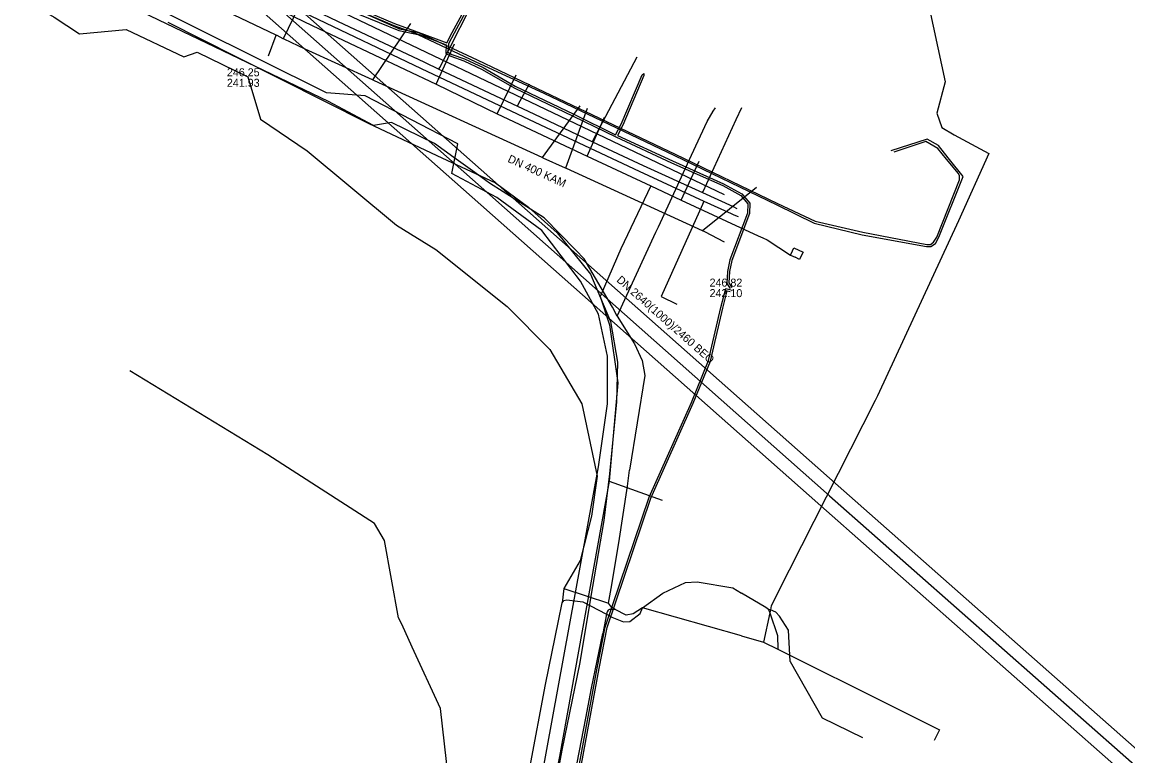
# Model space of a CAD drawing. Extents: x -600309 to -598967, y -1161267 to -1160292.
# Drawn here: x -600071.9 to -599961.4, y -1160914.1 to -1160840.8 of the extents above; entities that cross this region are included whole.
import ezdxf

# ---------------------------------------------------------------- set-up
doc = ezdxf.new("R2010")
doc.units = 0
for name, color, linetype in [('Vrstva 1', 7, 'Continuous'), ('Vrstva 12', 7, 'Continuous'), ('Vrstva 13', 7, 'Continuous'), ('Vrstva 19', 7, 'Continuous'), ('Vrstva 42', 7, 'Continuous'), ('Vrstva 44', 7, 'Continuous'), ('Vrstva 5', 7, 'Continuous'), ('Vrstva 51', 7, 'Continuous'), ('Vrstva 55', 7, 'Continuous'), ('Vrstva 58', 7, 'Continuous'), ('Vrstva 6', 7, 'Continuous'), ('Vrstva 8', 7, 'Continuous'), ('Vrstva 9', 7, 'Continuous')]:
    doc.layers.add(name, color=color, linetype=linetype)

msp = doc.modelspace()

# ---------------------------------------------------------------- linework, layer by layer
at = {"layer": 'Vrstva 1'}
msp.add_lwpolyline([(-600047.28, -1160844.11), (-600046.52, -1160842.06)], dxfattribs=at)
at = {"layer": 'Vrstva 12'}
for points in [[(-599972.93, -1160813.79), (-599978.49, -1160823.66), (-599978.82, -1160825.74), (-599980.3, -1160827.69), (-599982.73, -1160833.94), (-599981.57, -1160837.73), (-599979.64, -1160846.74), (-599980.47, -1160849.86), (-599979.98, -1160851.29), (-599978.75, -1160852.02)], [(-600091.66, -1160840.85), (-600091.96, -1160840.68), (-600094.05, -1160839.49), (-600086.91, -1160827.62), (-600086.16, -1160830.54), (-600077.15, -1160835.41), (-600068.71, -1160840.25), (-600066.18, -1160841.92), (-600061.52, -1160841.51), (-600055.76, -1160844.23), (-600054.42, -1160843.75), (-600049.36, -1160846.22)], [(-600028.74, -1160854.29), (-600030.68, -1160852.89), (-600035, -1160850.8), (-600036.79, -1160851.1), (-600041.29, -1160848.69), (-600064.77, -1160837.41)], [(-600049.36, -1160846.22), (-600048.09, -1160850.47)], [(-600003.44, -1160850.69), (-600002.82, -1160849.65)], [(-600002.82, -1160849.65), (-600002.61, -1160849.31)], [(-600048.09, -1160850.47), (-600043.43, -1160853.61), (-600034.48, -1160861.05), (-600030.54, -1160863.47), (-600023.43, -1160869.19), (-600019.17, -1160873.47), (-600015.95, -1160878.91), (-600014.41, -1160886.15), (-600014.98, -1160890.14), (-600016.13, -1160894.58), (-600017.76, -1160897.36)], [(-600005, -1160854.04), (-600003.44, -1160850.69)], [(-599978.75, -1160852.02), (-599975.28, -1160853.9), (-599978.3, -1160860.6), (-599986.39, -1160878.12), (-599986.62, -1160878.58), (-599995.22, -1160895.54), (-599997.03, -1160899.1), (-599997.11, -1160899.5)], [(-600026.67, -1160855.77), (-600028.74, -1160854.29)], [(-600008.57, -1160861.76), (-600008.31, -1160861.22), (-600005.8, -1160855.77), (-600005, -1160854.04)], [(-600012.43, -1160870.13), (-600012.89, -1160869.23), (-600015.71, -1160864.41), (-600016.55, -1160863.56), (-600019.74, -1160860.33), (-600025.19, -1160856.84), (-600026.67, -1160855.77)], [(-600012.43, -1160870.13), (-600008.57, -1160861.76)], [(-600012.43, -1160870.13), (-600010.68, -1160872.91), (-600009.94, -1160874.58), (-600009.67, -1160876.07), (-600011.18, -1160885.55)], [(-600011.38, -1160887.14), (-600011.18, -1160885.55)], [(-600013.04, -1160897.36), (-600012.27, -1160892.8), (-600011.38, -1160887.14)], [(-600017.76, -1160897.36), (-600017.94, -1160898.79)], [(-600017.76, -1160897.36), (-600013.28, -1160898.83)], [(-600013.28, -1160898.83), (-600013.04, -1160897.36)], [(-600009.88, -1160899.29), (-600007.86, -1160897.82), (-600005.6, -1160896.75)], [(-600005.6, -1160896.75), (-600004.42, -1160896.7), (-600000.86, -1160897.31), (-600000, -1160897.82)], [(-600017.94, -1160898.79), (-600017.76, -1160898.57), (-600017.45, -1160898.48), (-600015.86, -1160898.69), (-600013.49, -1160899.94)], [(-599997.29, -1160899.45), (-599997.56, -1160899.26), (-600000, -1160897.82)], [(-600018.3, -1160900.6), (-600017.94, -1160898.79)], [(-600013.49, -1160899.94), (-600012.96, -1160900.22), (-600011.78, -1160900.68), (-600011.17, -1160900.67), (-600010.12, -1160899.85), (-600009.88, -1160899.29)], [(-600012.62, -1160899.45), (-600013.19, -1160899.47), (-600013.33, -1160899.52), (-600013.44, -1160899.7), (-600013.49, -1160899.94)], [(-600012.62, -1160899.45), (-600013.01, -1160899.24), (-600013.28, -1160898.83)], [(-600009.88, -1160899.29), (-600010.84, -1160899.9), (-600011.53, -1160900.02), (-600012.62, -1160899.45)], [(-600000, -1160902.1), (-600009.88, -1160899.29)], [(-599997.17, -1160899.79), (-599997.79, -1160902.73)], [(-599997.29, -1160899.45), (-599997.17, -1160899.79)], [(-599997.11, -1160899.5), (-599997.29, -1160899.45)], [(-599997.11, -1160899.5), (-599997.17, -1160899.79)], [(-599997.17, -1160899.79), (-599996.39, -1160902.05), (-599996.38, -1160903.43)], [(-599995.17, -1160904.03), (-599995.3, -1160901.52), (-599996.2, -1160900.13), (-599996.56, -1160899.73), (-599997.11, -1160899.5)], [(-600021.41, -1160915.63), (-600021.16, -1160915.29), (-600019.58, -1160906.96), (-600018.3, -1160900.6)], [(-600013.49, -1160899.94), (-600013.87, -1160901.87)], [(-600022.47, -1160946.7), (-600022.17, -1160944.27), (-600018.18, -1160923.89), (-600015.57, -1160910.31), (-600014.99, -1160907.31), (-600013.87, -1160901.87)], [(-600000, -1160902.1), (-599997.79, -1160902.73)], [(-599997.79, -1160902.73), (-599996.38, -1160903.43)], [(-599996.38, -1160903.43), (-599995.17, -1160904.03)], [(-599995.15, -1160904.67), (-599995.17, -1160904.03)], [(-599995.17, -1160904.03), (-599986.06, -1160908.56)], [(-599995.15, -1160904.67), (-599991.92, -1160910.28)], [(-599986.06, -1160908.56), (-599980.21, -1160911.49), (-599980.74, -1160912.54)], [(-599991.92, -1160910.28), (-599987.89, -1160912.27)]]:
    msp.add_lwpolyline(points, dxfattribs=at)
at = {"layer": 'Vrstva 13'}
for p, q in [((-600001.04, -1160859.88), (-600000.77, -1160860)), ((-600000.84, -1160859.2), (-600000.47, -1160859.39)), ((-600000.77, -1160860), (-600000.34, -1160860.18))]:
    msp.add_line(p, q, dxfattribs=at)
for points in [[(-600075.2, -1160823.45), (-600070.43, -1160825.81), (-600064.32, -1160828.96), (-600054.38, -1160833.93), (-600053.49, -1160834.37), (-600042.61, -1160839.61), (-600040.39, -1160840.66), (-600031.7, -1160844.77), (-600030.24, -1160845.46), (-600022.4, -1160849.16), (-600020.77, -1160849.93), (-600014.89, -1160852.71), (-600009.83, -1160855.1), (-600003.91, -1160857.8), (-600000.84, -1160859.2)], [(-600075.91, -1160823.87), (-600070.68, -1160826.48), (-600064.69, -1160829.36), (-600053.95, -1160834.9), (-600043.04, -1160840.13), (-600032.02, -1160845.38), (-600021.22, -1160850.5), (-600010.24, -1160855.65), (-600003.77, -1160858.66), (-600001.04, -1160859.88)], [(-600030.24, -1160845.46), (-600030.15, -1160845.28), (-600026.13, -1160837.32)], [(-600014.89, -1160852.71), (-600014.82, -1160852.57), (-600010.42, -1160844.22)], [(-600022.4, -1160849.16), (-600022.31, -1160849), (-600021.18, -1160846.93)], [(-600003.91, -1160857.8), (-600003.84, -1160857.67), (-600000.54, -1160850.48), (-599999.98, -1160849.28)], [(-600003.77, -1160858.66), (-600003.89, -1160858.98), (-600008.03, -1160868.18), (-600006.47, -1160868.93)]]:
    msp.add_lwpolyline(points, dxfattribs=at)
at = {"layer": 'Vrstva 19'}
for points in [[(-600070.24, -1160827.89), (-600070.04, -1160828.01), (-600069.81, -1160828.12), (-600069.47, -1160828.3), (-600069.14, -1160828.43), (-600068.7, -1160828.63), (-600067.42, -1160829.27), (-600057.74, -1160833.93), (-600049.35, -1160838.07), (-600045.63, -1160839.81), (-600042.92, -1160841.09), (-600030.52, -1160846.95), (-600024.43, -1160849.93), (-600015.44, -1160854.15), (-600009.05, -1160857.12), (-600006.04, -1160858.54), (-599998.33, -1160862.11), (-599997.88, -1160862.32)], [(-600030.52, -1160846.95), (-600028.7, -1160842.91)], [(-600024.43, -1160849.93), (-600022.53, -1160846.02)], [(-600015.44, -1160854.15), (-600013.69, -1160850.24)], [(-600006.04, -1160858.54), (-600004.23, -1160854.64)], [(-600009.05, -1160857.12), (-600012.05, -1160863.42), (-600014.13, -1160868.17), (-600013.18, -1160871.01), (-600012.35, -1160876.81), (-600013.23, -1160886.63), (-600018.2, -1160914.15), (-600021.52, -1160930.87), (-600024.48, -1160949.96), (-600028.56, -1160971.82), (-600029.11, -1160974.77), (-600029.14, -1160974.99), (-600029.72, -1160978.77), (-600031.16, -1160990.94), (-600031.59, -1160993.91), (-600031.97, -1160996.52)], [(-599997.88, -1160862.32), (-599997.42, -1160862.53)], [(-599997.42, -1160862.53), (-599995.1, -1160864.04), (-599994.89, -1160863.6), (-599994.76, -1160863.32), (-599993.85, -1160863.75), (-599994.03, -1160864.11), (-599994.2, -1160864.47), (-599994.65, -1160864.25)], [(-599995.1, -1160864.04), (-599994.65, -1160864.25)], [(-600013.23, -1160886.63), (-600007.94, -1160888.52)]]:
    msp.add_lwpolyline(points, dxfattribs=at)
at = {"layer": 'Vrstva 42'}
for points in [[(-600037.52, -1160839.7), (-600034.67, -1160840.9), (-600031.69, -1160841.99), (-600029.98, -1160842.62), (-600029.46, -1160842.81), (-600028.91, -1160841.79), (-600027.1, -1160838.39)], [(-600026.93, -1160838.48), (-600028.72, -1160841.85), (-600029.3, -1160842.94), (-600029.37, -1160843.77), (-600028.96, -1160843.98), (-600027.69, -1160844.43), (-600025.81, -1160845.3), (-600022.63, -1160847.15), (-600016.76, -1160849.97), (-600012.58, -1160852.01), (-600012.04, -1160850.95), (-600009.94, -1160846.02), (-600009.77, -1160845.88), (-600009.76, -1160846.1), (-600011.85, -1160851.04), (-600012.4, -1160852.09), (-600006.9, -1160854.63), (-600001.79, -1160856.92), (-599999.96, -1160857.92), (-599999.16, -1160858.84), (-599999.2, -1160859.88), (-600000.96, -1160864.58), (-600001.21, -1160865.69), (-600001.26, -1160866.82), (-600000.98, -1160867.28)], [(-600037.6, -1160839.88), (-600034.75, -1160841.08), (-600031.75, -1160842.17), (-600029.51, -1160843.01), (-600029.57, -1160843.89), (-600029.04, -1160844.16), (-600027.77, -1160844.61), (-600025.91, -1160845.48), (-600022.73, -1160847.33), (-600016.84, -1160850.15), (-600012.57, -1160852.23), (-600006.98, -1160854.81), (-600001.87, -1160857.1), (-600000.08, -1160858.08), (-599999.36, -1160858.92), (-599999.4, -1160859.84), (-600001.16, -1160864.52), (-600001.41, -1160865.67), (-600001.46, -1160866.88), (-600001.14, -1160867.38)], [(-600028.08, -1160984.54), (-600027.7, -1160983.77), (-600026.59, -1160971.91), (-600024.56, -1160960.19), (-600024.34, -1160958.81), (-600022.15, -1160944.86), (-600021.22, -1160941.76), (-600018.11, -1160925.36), (-600014.43, -1160905.31), (-600013.63, -1160901.22), (-600009.24, -1160888.24), (-600005, -1160878.77), (-600003.3, -1160874.58), (-600002.06, -1160869.29), (-600001.57, -1160867.37), (-600001.04, -1160867.51)], [(-600027.88, -1160984.58), (-600027.5, -1160983.79), (-600026.4, -1160971.94), (-600024.37, -1160960.23), (-600024.14, -1160958.84), (-600021.96, -1160944.9), (-600021.03, -1160941.81), (-600017.92, -1160925.39), (-600014.23, -1160905.35), (-600013.44, -1160901.27), (-600009.05, -1160888.32), (-600004.82, -1160878.85), (-600003.11, -1160874.64), (-600001.87, -1160869.34), (-600001.42, -1160867.62), (-600001.12, -1160867.69)]]:
    msp.add_lwpolyline(points, dxfattribs=at)
at = {"layer": 'Vrstva 44'}
for points in [[(-600038.19, -1160840.01), (-600034.25, -1160841.61), (-600032.35, -1160841.99), (-600026.55, -1160844.71), (-600019.76, -1160847.85), (-600006.69, -1160854.1), (-599996.48, -1160859.02), (-599992.72, -1160860.85), (-599987.92, -1160862), (-599981.52, -1160863.17), (-599981.06, -1160863.18), (-599980.61, -1160862.87), (-599980.28, -1160862.26), (-599977.83, -1160856.17), (-599979.34, -1160854.31), (-599980.29, -1160853.09), (-599981.45, -1160852.46), (-599985.06, -1160853.63)], [(-600038.09, -1160839.71), (-600034.19, -1160841.43), (-600032.3, -1160841.8), (-600026.43, -1160844.51), (-600019.73, -1160847.71), (-600006.62, -1160853.94), (-599996.4, -1160858.88), (-599992.62, -1160860.65), (-599987.86, -1160861.75), (-599981.47, -1160862.98), (-599981.09, -1160862.99), (-599980.79, -1160862.76), (-599980.47, -1160862.24), (-599978.2, -1160856.51), (-599978.21, -1160856.13), (-599978.29, -1160855.87), (-599979.49, -1160854.44), (-599980.38, -1160853.4), (-599981.56, -1160852.69), (-599984.76, -1160853.76)]]:
    msp.add_lwpolyline(points, dxfattribs=at)
at = {"layer": 'Vrstva 5'}
msp.add_lwpolyline([(-600308.54, -1160606.85), (-600293.71, -1160619.85), (-600261.21, -1160648.62), (-600227.37, -1160678.98), (-600193.6, -1160708.94), (-600158.76, -1160739.74), (-600125.82, -1160768.91), (-600092.25, -1160798.69), (-600058.95, -1160828.11), (-600025.17, -1160858.03), (-599991.2, -1160888.1), (-599957.35, -1160917.96), (-599922.99, -1160948.3), (-599888.58, -1160978.69), (-599854.96, -1161008.36), (-599821.09, -1161038.33), (-599787.86, -1161071.18), (-599769.32, -1161098.46), (-599756.94, -1161125.32), (-599745.87, -1161159.88), (-599726.48, -1161222.14), (-599721.97, -1161234.03), (-599710.42, -1161267.03)], dxfattribs=at)
at = {"layer": 'Vrstva 51'}
msp.add_lwpolyline([(-600029.2, -1160995.83), (-600029.51, -1160995.11), (-600029.59, -1160994.65), (-600028.77, -1160988.2), (-600028.66, -1160978.14), (-600028.77, -1160969.29), (-600028.68, -1160967.03), (-600026.93, -1160957.82), (-600026.25, -1160954.04), (-600025.05, -1160948.56), (-600024.5, -1160945.47), (-600024.26, -1160944.09), (-600028.12, -1160937.72), (-600028.59, -1160929), (-600028.46, -1160923.79), (-600030.09, -1160909.34), (-600032.92, -1160903.21), (-600033.96, -1160900.94), (-600034.27, -1160900.28), (-600035.69, -1160892.55), (-600036.68, -1160890.87), (-600047.34, -1160884.01), (-600061.13, -1160875.61)], dxfattribs=at)
at = {"layer": 'Vrstva 55'}
for points in [[(-600038.64, -1160994.33), (-600031.63, -1160979.98), (-600014.29, -1160885.2), (-600013.39, -1160878.92), (-600013.39, -1160874.14), (-600014.29, -1160869.95), (-600016.08, -1160866.66), (-600019.97, -1160861.58), (-600024.45, -1160858.29), (-600028.94, -1160855.9), (-600028.34, -1160852.91), (-600037.61, -1160848.13), (-600041.5, -1160847.83), (-600061.23, -1160837.96), (-600071.2, -1160833.38), (-600081.26, -1160829.89), (-600090.32, -1160825.04), (-600085.27, -1160815.83)], [(-600054.61, -1160832.69), (-600001.73, -1160857.99)]]:
    msp.add_lwpolyline(points, dxfattribs=at)
at = {"layer": 'Vrstva 58'}
for points in [[(-600057.36, -1160840.75), (-600050.56, -1160844.19), (-600037.33, -1160850.84), (-600030.47, -1160854.1), (-600024.58, -1160856.83), (-600021.3, -1160859.25)], [(-600021.3, -1160859.25), (-600018.42, -1160861.81), (-600015.09, -1160865.96), (-600013.11, -1160870.69), (-600012.4, -1160874.75), (-600012.5, -1160878.7), (-600013.21, -1160885.89), (-600013.77, -1160890.56), (-600015.09, -1160898.33), (-600016.17, -1160904.75), (-600017.96, -1160913.53), (-600019.34, -1160920.89)], [(-600029.21, -1160995.84), (-600029.51, -1160995.11), (-600029.59, -1160994.65), (-600028.77, -1160988.2), (-600028.66, -1160978.14), (-600028.77, -1160969.29), (-600028.68, -1160967.03), (-600026.93, -1160957.82), (-600026.25, -1160954.04), (-600025.05, -1160948.56), (-600024.5, -1160945.47), (-600024.26, -1160944.09), (-600028.12, -1160937.72), (-600028.59, -1160929), (-600028.46, -1160923.79), (-600030.09, -1160909.34), (-600032.92, -1160903.21), (-600033.96, -1160900.94), (-600034.27, -1160900.28), (-600035.69, -1160892.55), (-600036.68, -1160890.87), (-600047.34, -1160884.01), (-600061.13, -1160875.61)]]:
    msp.add_lwpolyline(points, dxfattribs=at)
at = {"layer": 'Vrstva 6'}
for points in [[(-600308.54, -1160605.1), (-600292.84, -1160618.86), (-600260.33, -1160647.63), (-600226.49, -1160677.99), (-600192.72, -1160707.95), (-600157.88, -1160738.75), (-600124.94, -1160767.92), (-600091.37, -1160797.7), (-600058.07, -1160827.12), (-600024.29, -1160857.04), (-599990.32, -1160887.11), (-599956.48, -1160916.97), (-599922.11, -1160947.31), (-599887.7, -1160977.7), (-599854.08, -1161007.37), (-599820.19, -1161037.36), (-599786.84, -1161070.33), (-599768.16, -1161097.81), (-599755.71, -1161124.84), (-599744.61, -1161159.48), (-599725.23, -1161221.71), (-599720.73, -1161233.58), (-599709.02, -1161267.03)], [(-599711.82, -1161267.03), (-599723.21, -1161234.48), (-599727.73, -1161222.57), (-599747.13, -1161160.27), (-599758.17, -1161125.8), (-599770.48, -1161099.11), (-599788.88, -1161072.03), (-599821.99, -1161039.3), (-599855.84, -1161009.35), (-599889.46, -1160979.68), (-599923.87, -1160949.29), (-599958.23, -1160918.95), (-599992.08, -1160889.09), (-600026.05, -1160859.02), (-600059.83, -1160829.1), (-600093.13, -1160799.68), (-600126.7, -1160769.9), (-600159.64, -1160740.73), (-600194.48, -1160709.93), (-600228.25, -1160679.97), (-600262.09, -1160649.61), (-600294.58, -1160620.84), (-600308.54, -1160608.61)]]:
    msp.add_lwpolyline(points, dxfattribs=at)
at = {"layer": 'Vrstva 9'}
for p, q in [((-600042.95, -1160836.49), (-600045.8, -1160842.41)), ((-600033.09, -1160840.91), (-600036.87, -1160846.54)), ((-600016.16, -1160849.12), (-600019.91, -1160854.29)), ((-600015.44, -1160849.39), (-600017.59, -1160855.35)), ((-599998.51, -1160857.3), (-600003.91, -1160861.61))]:
    msp.add_line(p, q, dxfattribs=at)
for points in [[(-600043.6, -1160843.46), (-600045.71, -1160842.45), (-600045.8, -1160842.41), (-600046.43, -1160842.1), (-600046.52, -1160842.06), (-600052.87, -1160839.03), (-600052.97, -1160838.98), (-600070.39, -1160830.66), (-600070.56, -1160830.58), (-600082.75, -1160824.76)], [(-600001.71, -1160862.74), (-600003.68, -1160861.73), (-600003.91, -1160861.61), (-600017.49, -1160855.4), (-600017.59, -1160855.35), (-600019.81, -1160854.34), (-600019.91, -1160854.29), (-600036.7, -1160846.61), (-600036.87, -1160846.54), (-600043.6, -1160843.46)]]:
    msp.add_lwpolyline(points, dxfattribs=at)

# ---------------------------------------------------------------- texts
at = {"layer": 'Vrstva 12'}
for s, p in [('246.25', (-600051.44, -1160846.17)), ('241.93', (-600051.44, -1160847.22)), ('246.82', (-600003.19, -1160867.19)), ('242.10', (-600003.19, -1160868.24))]:
    msp.add_text(s, height=0.8, dxfattribs=at).set_placement(p)
msp.add_text('DN 400 KAM', height=0.8, rotation=335.4095, dxfattribs=at).set_placement((-600023.44, -1160854.7))
at = {"layer": 'Vrstva 8'}
msp.add_text('DN 2640(1000)/2460 BEO', height=0.8, rotation=318.5072, dxfattribs=at).set_placement((-600012.55, -1160866.62))

doc.saveas('drawing.dxf')
